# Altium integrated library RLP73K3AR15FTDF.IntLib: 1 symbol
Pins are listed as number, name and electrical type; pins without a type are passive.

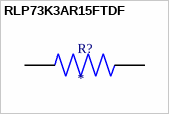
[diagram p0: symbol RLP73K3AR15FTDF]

## RLP73K3AR15FTDF
designator R?
RLP73K 3A R15 1% 1K RL; MP: RLP73K3AR15FTDF
footprint RESC6331X70N
pins: 1, 2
